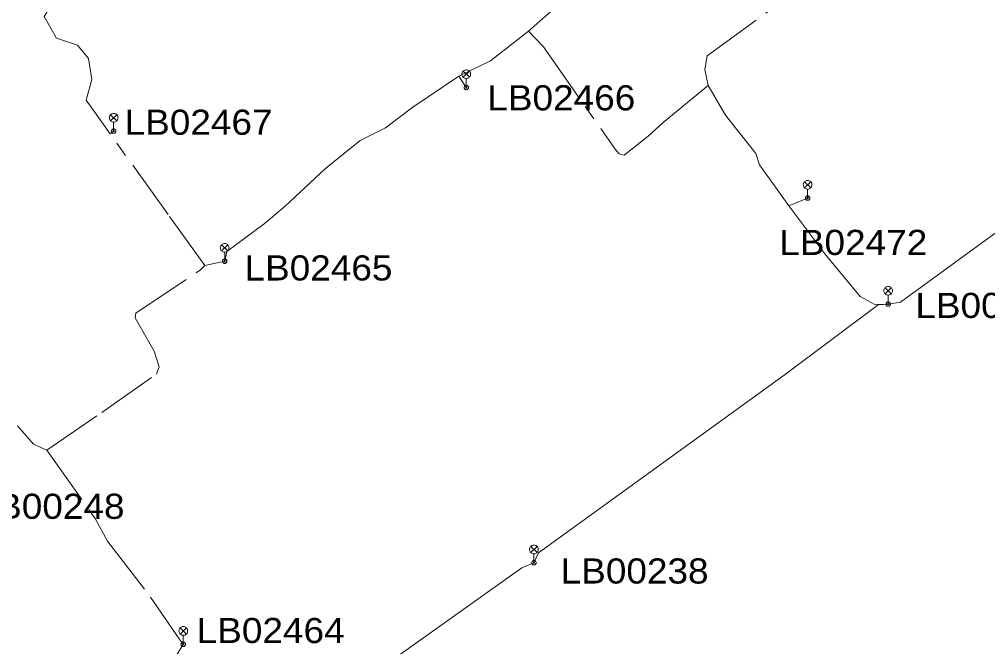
# Model space of a CAD drawing. Extents: x -688049 to -687261, y -973611 to -973038.
# Drawn here: x -687766.3 to -687682.8, y -973481.6 to -973427.5 of the extents above; entities that cross this region are included whole.
import ezdxf

# ---------------------------------------------------------------- set-up
doc = ezdxf.new("R2010")
doc.units = 0
doc.header["$LTSCALE"] = 0.87
doc.linetypes.add('LONG_DASH_SHORT_DASH', pattern=[9.9, 6, -1.2, 1.5, -1.2])
doc.layers.add('1', color=7, linetype='Continuous', lineweight=13)

msp = doc.modelspace()

# ---------------------------------------------------------------- linework, layer by layer
at = {"layer": '1'}
for p, q in [((-687728.025, -973431.965), (-687727.495, -973432.495)), ((-687728.025, -973432.495), (-687727.495, -973431.965)), ((-687727.76, -973433.38), (-687727.76, -973432.605)), ((-687758.455, -973435.725), (-687757.925, -973436.255)), ((-687758.455, -973436.255), (-687757.925, -973435.725)), ((-687758.19, -973437.14), (-687758.19, -973436.365)), ((-687698.565, -973441.505), (-687698.035, -973442.035)), ((-687698.565, -973442.035), (-687698.035, -973441.505)), ((-687698.3, -973442.92), (-687698.3, -973442.145)), ((-687748.875, -973446.945), (-687748.345, -973447.475)), ((-687748.875, -973447.475), (-687748.345, -973446.945)), ((-687748.61, -973448.36), (-687748.61, -973447.585)), ((-687691.615, -973450.645), (-687691.085, -973451.175)), ((-687691.615, -973451.175), (-687691.085, -973450.645)), ((-687691.35, -973452.06), (-687691.35, -973451.285)), ((-687722.185, -973472.955), (-687721.655, -973473.485)), ((-687722.185, -973473.485), (-687721.655, -973472.955)), ((-687721.92, -973474.37), (-687721.92, -973473.595)), ((-687752.445, -973479.985), (-687751.915, -973480.515)), ((-687752.445, -973480.515), (-687751.915, -973479.985)), ((-687752.18, -973481.4), (-687752.18, -973480.625))]:
    msp.add_line(p, q, dxfattribs=at)
at = {"layer": '1', "linetype": 'LONG_DASH_SHORT_DASH'}
for p, q in [((-687728.39, -973432.41), (-687727.76, -973433.38)), ((-687758.5, -973437.37), (-687758.19, -973437.14)), ((-687699.92, -973443.59), (-687698.3, -973442.92)), ((-687750.33, -973448.73), (-687748.61, -973448.36))]:
    msp.add_line(p, q, dxfattribs=at)
for points in [[(-687724.92, -973418.37), (-687719.49, -973425.59), (-687719.72, -973426.17), (-687722.38, -973428.53)], [(-687758.5, -973437.37), (-687760.56, -973434.47), (-687760.07, -973432.69), (-687760.35, -973430.88), (-687761.31, -973429.72), (-687763.11, -973429.13), (-687764.19, -973427.27), (-687763.32, -973425.88)], [(-687706.89, -973433.2), (-687707.18, -973431.82), (-687706.97, -973430.66), (-687700.3, -973425.8), (-687699.51, -973425.76)], [(-687722.38, -973428.53), (-687725.67, -973431.08), (-687728.39, -973432.41)], [(-687722.38, -973428.53), (-687721.1, -973429.88), (-687714.91, -973438.69), (-687714.57, -973439.11), (-687714.12, -973439.23), (-687712.06, -973437.58), (-687710.76, -973436.4), (-687706.89, -973433.2)], [(-687728.39, -973432.41), (-687732.37, -973435.09), (-687734.72, -973436.87), (-687736.91, -973437.95), (-687739.91, -973440.38), (-687743.38, -973443.62), (-687745.19, -973445.14), (-687748.41, -973447.53), (-687748.61, -973448.36)], [(-687699.92, -973443.59), (-687702.46, -973440.06), (-687702.77, -973439.08), (-687705.4, -973435.77), (-687706.89, -973433.2)], [(-687750.33, -973448.73), (-687753.5, -973444.33), (-687758.5, -973437.37)], [(-687691.34, -973452.07), (-687692.5, -973452.1), (-687693.77, -973451.41), (-687696.82, -973447.73), (-687699.92, -973443.59)], [(-687763.95, -973464.66), (-687759.21, -973461.4), (-687754.5, -973458.1), (-687754.26, -973457.46), (-687754.69, -973456.12), (-687756.33, -973453.24), (-687756.28, -973452.84), (-687750.71, -973449.12), (-687750.33, -973448.73)], [(-687766.48, -973462.57), (-687765.11, -973464.15), (-687763.95, -973464.66)], [(-687763.95, -973464.66), (-687759.79, -973470.54), (-687758.71, -973472.52), (-687755.01, -973477.33), (-687752.54, -973480.93), (-687752.18, -973481.4)], [(-687752.18, -973481.4), (-687752.93, -973482.67), (-687750.74, -973485.73), (-687749.13, -973487.38), (-687746.86, -973490.22), (-687747.02, -973490.93), (-687750.43, -973493.25), (-687752.29, -973494.69), (-687752.34, -973494.74)]]:
    msp.add_lwpolyline(points, dxfattribs=at)
at = {"layer": '1'}
for points in [[(-687727.385, -973432.23), (-687727.391, -973432.165), (-687727.408, -973432.102), (-687727.435, -973432.043), (-687727.473, -973431.989), (-687727.519, -973431.943), (-687727.572, -973431.905), (-687727.632, -973431.878), (-687727.695, -973431.861), (-687727.76, -973431.855), (-687727.825, -973431.861), (-687727.888, -973431.878), (-687727.948, -973431.905), (-687728.001, -973431.943), (-687728.047, -973431.989), (-687728.085, -973432.043), (-687728.112, -973432.102), (-687728.129, -973432.165), (-687728.135, -973432.23), (-687728.129, -973432.295), (-687728.112, -973432.358), (-687728.085, -973432.418), (-687728.047, -973432.471), (-687728.001, -973432.517), (-687727.948, -973432.555), (-687727.888, -973432.582), (-687727.825, -973432.599), (-687727.76, -973432.605), (-687727.695, -973432.599), (-687727.632, -973432.582), (-687727.572, -973432.555), (-687727.519, -973432.517), (-687727.473, -973432.471), (-687727.435, -973432.418), (-687727.408, -973432.358), (-687727.391, -973432.295)], [(-687727.57, -973433.38), (-687727.573, -973433.347), (-687727.581, -973433.315), (-687727.595, -973433.285), (-687727.614, -973433.258), (-687727.638, -973433.234), (-687727.665, -973433.215), (-687727.695, -973433.201), (-687727.727, -973433.193), (-687727.76, -973433.19), (-687727.793, -973433.193), (-687727.825, -973433.201), (-687727.855, -973433.215), (-687727.882, -973433.234), (-687727.906, -973433.258), (-687727.925, -973433.285), (-687727.939, -973433.315), (-687727.947, -973433.347), (-687727.95, -973433.38), (-687727.947, -973433.413), (-687727.939, -973433.445), (-687727.925, -973433.475), (-687727.906, -973433.502), (-687727.882, -973433.526), (-687727.855, -973433.545), (-687727.825, -973433.559), (-687727.793, -973433.567), (-687727.76, -973433.57), (-687727.727, -973433.567), (-687727.695, -973433.559), (-687727.665, -973433.545), (-687727.638, -973433.526), (-687727.614, -973433.502), (-687727.595, -973433.475), (-687727.581, -973433.445), (-687727.573, -973433.413)], [(-687727.71, -973433.38), (-687727.711, -973433.371), (-687727.713, -973433.363), (-687727.717, -973433.355), (-687727.722, -973433.348), (-687727.728, -973433.342), (-687727.735, -973433.337), (-687727.743, -973433.333), (-687727.751, -973433.331), (-687727.76, -973433.33), (-687727.769, -973433.331), (-687727.777, -973433.333), (-687727.785, -973433.337), (-687727.792, -973433.342), (-687727.798, -973433.348), (-687727.803, -973433.355), (-687727.807, -973433.363), (-687727.809, -973433.371), (-687727.81, -973433.38), (-687727.809, -973433.389), (-687727.807, -973433.397), (-687727.803, -973433.405), (-687727.798, -973433.412), (-687727.792, -973433.418), (-687727.785, -973433.423), (-687727.777, -973433.427), (-687727.769, -973433.429), (-687727.76, -973433.43), (-687727.751, -973433.429), (-687727.743, -973433.427), (-687727.735, -973433.423), (-687727.728, -973433.418), (-687727.722, -973433.412), (-687727.717, -973433.405), (-687727.713, -973433.397), (-687727.711, -973433.389)], [(-687757.815, -973435.99), (-687757.821, -973435.925), (-687757.838, -973435.862), (-687757.865, -973435.802), (-687757.903, -973435.749), (-687757.949, -973435.703), (-687758.003, -973435.665), (-687758.062, -973435.638), (-687758.125, -973435.621), (-687758.19, -973435.615), (-687758.255, -973435.621), (-687758.318, -973435.638), (-687758.378, -973435.665), (-687758.431, -973435.703), (-687758.477, -973435.749), (-687758.515, -973435.802), (-687758.542, -973435.862), (-687758.559, -973435.925), (-687758.565, -973435.99), (-687758.559, -973436.055), (-687758.542, -973436.118), (-687758.515, -973436.178), (-687758.477, -973436.231), (-687758.431, -973436.277), (-687758.378, -973436.315), (-687758.318, -973436.342), (-687758.255, -973436.359), (-687758.19, -973436.365), (-687758.125, -973436.359), (-687758.062, -973436.342), (-687758.003, -973436.315), (-687757.949, -973436.277), (-687757.903, -973436.231), (-687757.865, -973436.178), (-687757.838, -973436.118), (-687757.821, -973436.055)], [(-687758, -973437.14), (-687758.003, -973437.107), (-687758.011, -973437.075), (-687758.025, -973437.045), (-687758.044, -973437.018), (-687758.068, -973436.994), (-687758.095, -973436.975), (-687758.125, -973436.961), (-687758.157, -973436.953), (-687758.19, -973436.95), (-687758.223, -973436.953), (-687758.255, -973436.961), (-687758.285, -973436.975), (-687758.312, -973436.994), (-687758.336, -973437.018), (-687758.355, -973437.045), (-687758.369, -973437.075), (-687758.377, -973437.107), (-687758.38, -973437.14), (-687758.377, -973437.173), (-687758.369, -973437.205), (-687758.355, -973437.235), (-687758.336, -973437.262), (-687758.312, -973437.286), (-687758.285, -973437.305), (-687758.255, -973437.319), (-687758.223, -973437.327), (-687758.19, -973437.33), (-687758.157, -973437.327), (-687758.125, -973437.319), (-687758.095, -973437.305), (-687758.068, -973437.286), (-687758.044, -973437.262), (-687758.025, -973437.235), (-687758.011, -973437.205), (-687758.003, -973437.173)], [(-687758.14, -973437.14), (-687758.141, -973437.131), (-687758.143, -973437.123), (-687758.147, -973437.115), (-687758.152, -973437.108), (-687758.158, -973437.102), (-687758.165, -973437.097), (-687758.173, -973437.093), (-687758.181, -973437.091), (-687758.19, -973437.09), (-687758.199, -973437.091), (-687758.207, -973437.093), (-687758.215, -973437.097), (-687758.222, -973437.102), (-687758.228, -973437.108), (-687758.233, -973437.115), (-687758.237, -973437.123), (-687758.239, -973437.131), (-687758.24, -973437.14), (-687758.239, -973437.149), (-687758.237, -973437.157), (-687758.233, -973437.165), (-687758.228, -973437.172), (-687758.222, -973437.178), (-687758.215, -973437.183), (-687758.207, -973437.187), (-687758.199, -973437.189), (-687758.19, -973437.19), (-687758.181, -973437.189), (-687758.173, -973437.187), (-687758.165, -973437.183), (-687758.158, -973437.178), (-687758.152, -973437.172), (-687758.147, -973437.165), (-687758.143, -973437.157), (-687758.141, -973437.149)], [(-687697.925, -973441.77), (-687697.931, -973441.705), (-687697.948, -973441.642), (-687697.975, -973441.582), (-687698.013, -973441.529), (-687698.059, -973441.483), (-687698.112, -973441.445), (-687698.172, -973441.418), (-687698.235, -973441.401), (-687698.3, -973441.395), (-687698.365, -973441.401), (-687698.428, -973441.418), (-687698.488, -973441.445), (-687698.541, -973441.483), (-687698.587, -973441.529), (-687698.625, -973441.582), (-687698.652, -973441.642), (-687698.669, -973441.705), (-687698.675, -973441.77), (-687698.669, -973441.835), (-687698.652, -973441.898), (-687698.625, -973441.958), (-687698.587, -973442.011), (-687698.541, -973442.057), (-687698.488, -973442.095), (-687698.428, -973442.122), (-687698.365, -973442.139), (-687698.3, -973442.145), (-687698.235, -973442.139), (-687698.172, -973442.122), (-687698.112, -973442.095), (-687698.059, -973442.057), (-687698.013, -973442.011), (-687697.975, -973441.958), (-687697.948, -973441.898), (-687697.931, -973441.835)], [(-687698.11, -973442.92), (-687698.113, -973442.887), (-687698.121, -973442.855), (-687698.135, -973442.825), (-687698.154, -973442.798), (-687698.178, -973442.774), (-687698.205, -973442.755), (-687698.235, -973442.741), (-687698.267, -973442.733), (-687698.3, -973442.73), (-687698.333, -973442.733), (-687698.365, -973442.741), (-687698.395, -973442.755), (-687698.422, -973442.774), (-687698.446, -973442.798), (-687698.465, -973442.825), (-687698.479, -973442.855), (-687698.487, -973442.887), (-687698.49, -973442.92), (-687698.487, -973442.953), (-687698.479, -973442.985), (-687698.465, -973443.015), (-687698.446, -973443.042), (-687698.422, -973443.066), (-687698.395, -973443.085), (-687698.365, -973443.099), (-687698.333, -973443.107), (-687698.3, -973443.11), (-687698.267, -973443.107), (-687698.235, -973443.099), (-687698.205, -973443.085), (-687698.178, -973443.066), (-687698.154, -973443.042), (-687698.135, -973443.015), (-687698.121, -973442.985), (-687698.113, -973442.953)], [(-687698.25, -973442.92), (-687698.251, -973442.911), (-687698.253, -973442.903), (-687698.257, -973442.895), (-687698.262, -973442.888), (-687698.268, -973442.882), (-687698.275, -973442.877), (-687698.283, -973442.873), (-687698.291, -973442.871), (-687698.3, -973442.87), (-687698.309, -973442.871), (-687698.317, -973442.873), (-687698.325, -973442.877), (-687698.332, -973442.882), (-687698.338, -973442.888), (-687698.343, -973442.895), (-687698.347, -973442.903), (-687698.349, -973442.911), (-687698.35, -973442.92), (-687698.349, -973442.929), (-687698.347, -973442.937), (-687698.343, -973442.945), (-687698.338, -973442.952), (-687698.332, -973442.958), (-687698.325, -973442.963), (-687698.317, -973442.967), (-687698.309, -973442.969), (-687698.3, -973442.97), (-687698.291, -973442.969), (-687698.283, -973442.967), (-687698.275, -973442.963), (-687698.268, -973442.958), (-687698.262, -973442.952), (-687698.257, -973442.945), (-687698.253, -973442.937), (-687698.251, -973442.929)], [(-687748.235, -973447.21), (-687748.241, -973447.145), (-687748.258, -973447.082), (-687748.285, -973447.022), (-687748.323, -973446.969), (-687748.369, -973446.923), (-687748.422, -973446.885), (-687748.482, -973446.858), (-687748.545, -973446.841), (-687748.61, -973446.835), (-687748.675, -973446.841), (-687748.738, -973446.858), (-687748.798, -973446.885), (-687748.851, -973446.923), (-687748.897, -973446.969), (-687748.935, -973447.022), (-687748.962, -973447.082), (-687748.979, -973447.145), (-687748.985, -973447.21), (-687748.979, -973447.275), (-687748.962, -973447.338), (-687748.935, -973447.398), (-687748.897, -973447.451), (-687748.851, -973447.497), (-687748.798, -973447.535), (-687748.738, -973447.562), (-687748.675, -973447.579), (-687748.61, -973447.585), (-687748.545, -973447.579), (-687748.482, -973447.562), (-687748.422, -973447.535), (-687748.369, -973447.497), (-687748.323, -973447.451), (-687748.285, -973447.398), (-687748.258, -973447.338), (-687748.241, -973447.275)], [(-687748.42, -973448.36), (-687748.423, -973448.327), (-687748.431, -973448.295), (-687748.445, -973448.265), (-687748.464, -973448.238), (-687748.488, -973448.214), (-687748.515, -973448.195), (-687748.545, -973448.181), (-687748.577, -973448.173), (-687748.61, -973448.17), (-687748.643, -973448.173), (-687748.675, -973448.181), (-687748.705, -973448.195), (-687748.732, -973448.214), (-687748.756, -973448.238), (-687748.775, -973448.265), (-687748.789, -973448.295), (-687748.797, -973448.327), (-687748.8, -973448.36), (-687748.797, -973448.393), (-687748.789, -973448.425), (-687748.775, -973448.455), (-687748.756, -973448.482), (-687748.732, -973448.506), (-687748.705, -973448.525), (-687748.675, -973448.539), (-687748.643, -973448.547), (-687748.61, -973448.55), (-687748.577, -973448.547), (-687748.545, -973448.539), (-687748.515, -973448.525), (-687748.488, -973448.506), (-687748.464, -973448.482), (-687748.445, -973448.455), (-687748.431, -973448.425), (-687748.423, -973448.393)], [(-687748.56, -973448.36), (-687748.561, -973448.351), (-687748.563, -973448.343), (-687748.567, -973448.335), (-687748.572, -973448.328), (-687748.578, -973448.322), (-687748.585, -973448.317), (-687748.593, -973448.313), (-687748.601, -973448.311), (-687748.61, -973448.31), (-687748.619, -973448.311), (-687748.627, -973448.313), (-687748.635, -973448.317), (-687748.642, -973448.322), (-687748.648, -973448.328), (-687748.653, -973448.335), (-687748.657, -973448.343), (-687748.659, -973448.351), (-687748.66, -973448.36), (-687748.659, -973448.369), (-687748.657, -973448.377), (-687748.653, -973448.385), (-687748.648, -973448.392), (-687748.642, -973448.398), (-687748.635, -973448.403), (-687748.627, -973448.407), (-687748.619, -973448.409), (-687748.61, -973448.41), (-687748.601, -973448.409), (-687748.593, -973448.407), (-687748.585, -973448.403), (-687748.578, -973448.398), (-687748.572, -973448.392), (-687748.567, -973448.385), (-687748.563, -973448.377), (-687748.561, -973448.369)], [(-687690.975, -973450.91), (-687690.981, -973450.845), (-687690.998, -973450.782), (-687691.025, -973450.722), (-687691.063, -973450.669), (-687691.109, -973450.623), (-687691.162, -973450.585), (-687691.222, -973450.558), (-687691.285, -973450.541), (-687691.35, -973450.535), (-687691.415, -973450.541), (-687691.478, -973450.558), (-687691.538, -973450.585), (-687691.591, -973450.623), (-687691.637, -973450.669), (-687691.675, -973450.722), (-687691.702, -973450.782), (-687691.719, -973450.845), (-687691.725, -973450.91), (-687691.719, -973450.975), (-687691.702, -973451.038), (-687691.675, -973451.098), (-687691.637, -973451.151), (-687691.591, -973451.197), (-687691.538, -973451.235), (-687691.478, -973451.262), (-687691.415, -973451.279), (-687691.35, -973451.285), (-687691.285, -973451.279), (-687691.222, -973451.262), (-687691.162, -973451.235), (-687691.109, -973451.197), (-687691.063, -973451.151), (-687691.025, -973451.098), (-687690.998, -973451.038), (-687690.981, -973450.975)], [(-687691.16, -973452.06), (-687691.163, -973452.027), (-687691.171, -973451.995), (-687691.185, -973451.965), (-687691.204, -973451.938), (-687691.228, -973451.914), (-687691.255, -973451.895), (-687691.285, -973451.881), (-687691.317, -973451.873), (-687691.35, -973451.87), (-687691.383, -973451.873), (-687691.415, -973451.881), (-687691.445, -973451.895), (-687691.472, -973451.914), (-687691.496, -973451.938), (-687691.515, -973451.965), (-687691.529, -973451.995), (-687691.537, -973452.027), (-687691.54, -973452.06), (-687691.537, -973452.093), (-687691.529, -973452.125), (-687691.515, -973452.155), (-687691.496, -973452.182), (-687691.472, -973452.206), (-687691.445, -973452.225), (-687691.415, -973452.239), (-687691.383, -973452.247), (-687691.35, -973452.25), (-687691.317, -973452.247), (-687691.285, -973452.239), (-687691.255, -973452.225), (-687691.228, -973452.206), (-687691.204, -973452.182), (-687691.185, -973452.155), (-687691.171, -973452.125), (-687691.163, -973452.093)], [(-687691.3, -973452.06), (-687691.301, -973452.051), (-687691.303, -973452.043), (-687691.307, -973452.035), (-687691.312, -973452.028), (-687691.318, -973452.022), (-687691.325, -973452.017), (-687691.333, -973452.013), (-687691.341, -973452.011), (-687691.35, -973452.01), (-687691.359, -973452.011), (-687691.367, -973452.013), (-687691.375, -973452.017), (-687691.382, -973452.022), (-687691.388, -973452.028), (-687691.393, -973452.035), (-687691.397, -973452.043), (-687691.399, -973452.051), (-687691.4, -973452.06), (-687691.399, -973452.069), (-687691.397, -973452.077), (-687691.393, -973452.085), (-687691.388, -973452.092), (-687691.382, -973452.098), (-687691.375, -973452.103), (-687691.367, -973452.107), (-687691.359, -973452.109), (-687691.35, -973452.11), (-687691.341, -973452.109), (-687691.333, -973452.107), (-687691.325, -973452.103), (-687691.318, -973452.098), (-687691.312, -973452.092), (-687691.307, -973452.085), (-687691.303, -973452.077), (-687691.301, -973452.069)], [(-687721.545, -973473.22), (-687721.551, -973473.155), (-687721.568, -973473.092), (-687721.595, -973473.033), (-687721.633, -973472.979), (-687721.679, -973472.933), (-687721.732, -973472.895), (-687721.792, -973472.868), (-687721.855, -973472.851), (-687721.92, -973472.845), (-687721.985, -973472.851), (-687722.048, -973472.868), (-687722.108, -973472.895), (-687722.161, -973472.933), (-687722.207, -973472.979), (-687722.245, -973473.033), (-687722.272, -973473.092), (-687722.289, -973473.155), (-687722.295, -973473.22), (-687722.289, -973473.285), (-687722.272, -973473.348), (-687722.245, -973473.408), (-687722.207, -973473.461), (-687722.161, -973473.507), (-687722.108, -973473.545), (-687722.048, -973473.572), (-687721.985, -973473.589), (-687721.92, -973473.595), (-687721.855, -973473.589), (-687721.792, -973473.572), (-687721.732, -973473.545), (-687721.679, -973473.507), (-687721.633, -973473.461), (-687721.595, -973473.408), (-687721.568, -973473.348), (-687721.551, -973473.285)], [(-687721.73, -973474.37), (-687721.733, -973474.337), (-687721.741, -973474.305), (-687721.755, -973474.275), (-687721.774, -973474.248), (-687721.798, -973474.224), (-687721.825, -973474.205), (-687721.855, -973474.191), (-687721.887, -973474.183), (-687721.92, -973474.18), (-687721.953, -973474.183), (-687721.985, -973474.191), (-687722.015, -973474.205), (-687722.042, -973474.224), (-687722.066, -973474.248), (-687722.085, -973474.275), (-687722.099, -973474.305), (-687722.107, -973474.337), (-687722.11, -973474.37), (-687722.107, -973474.403), (-687722.099, -973474.435), (-687722.085, -973474.465), (-687722.066, -973474.492), (-687722.042, -973474.516), (-687722.015, -973474.535), (-687721.985, -973474.549), (-687721.953, -973474.557), (-687721.92, -973474.56), (-687721.887, -973474.557), (-687721.855, -973474.549), (-687721.825, -973474.535), (-687721.798, -973474.516), (-687721.774, -973474.492), (-687721.755, -973474.465), (-687721.741, -973474.435), (-687721.733, -973474.403)], [(-687721.87, -973474.37), (-687721.871, -973474.361), (-687721.873, -973474.353), (-687721.877, -973474.345), (-687721.882, -973474.338), (-687721.888, -973474.332), (-687721.895, -973474.327), (-687721.903, -973474.323), (-687721.911, -973474.321), (-687721.92, -973474.32), (-687721.929, -973474.321), (-687721.937, -973474.323), (-687721.945, -973474.327), (-687721.952, -973474.332), (-687721.958, -973474.338), (-687721.963, -973474.345), (-687721.967, -973474.353), (-687721.969, -973474.361), (-687721.97, -973474.37), (-687721.969, -973474.379), (-687721.967, -973474.387), (-687721.963, -973474.395), (-687721.958, -973474.402), (-687721.952, -973474.408), (-687721.945, -973474.413), (-687721.937, -973474.417), (-687721.929, -973474.419), (-687721.92, -973474.42), (-687721.911, -973474.419), (-687721.903, -973474.417), (-687721.895, -973474.413), (-687721.888, -973474.408), (-687721.882, -973474.402), (-687721.877, -973474.395), (-687721.873, -973474.387), (-687721.871, -973474.379)], [(-687751.805, -973480.25), (-687751.811, -973480.185), (-687751.828, -973480.122), (-687751.855, -973480.062), (-687751.893, -973480.009), (-687751.939, -973479.963), (-687751.992, -973479.925), (-687752.052, -973479.898), (-687752.115, -973479.881), (-687752.18, -973479.875), (-687752.245, -973479.881), (-687752.308, -973479.898), (-687752.368, -973479.925), (-687752.421, -973479.963), (-687752.467, -973480.009), (-687752.505, -973480.062), (-687752.532, -973480.122), (-687752.549, -973480.185), (-687752.555, -973480.25), (-687752.549, -973480.315), (-687752.532, -973480.378), (-687752.505, -973480.438), (-687752.467, -973480.491), (-687752.421, -973480.537), (-687752.368, -973480.575), (-687752.308, -973480.602), (-687752.245, -973480.619), (-687752.18, -973480.625), (-687752.115, -973480.619), (-687752.052, -973480.602), (-687751.992, -973480.575), (-687751.939, -973480.537), (-687751.893, -973480.491), (-687751.855, -973480.438), (-687751.828, -973480.378), (-687751.811, -973480.315)], [(-687751.99, -973481.4), (-687751.993, -973481.367), (-687752.001, -973481.335), (-687752.015, -973481.305), (-687752.034, -973481.278), (-687752.058, -973481.254), (-687752.085, -973481.235), (-687752.115, -973481.221), (-687752.147, -973481.213), (-687752.18, -973481.21), (-687752.213, -973481.213), (-687752.245, -973481.221), (-687752.275, -973481.235), (-687752.302, -973481.254), (-687752.326, -973481.278), (-687752.345, -973481.305), (-687752.359, -973481.335), (-687752.367, -973481.367), (-687752.37, -973481.4), (-687752.367, -973481.433), (-687752.359, -973481.465), (-687752.345, -973481.495), (-687752.326, -973481.522), (-687752.302, -973481.546), (-687752.275, -973481.565), (-687752.245, -973481.579), (-687752.213, -973481.587), (-687752.18, -973481.59), (-687752.147, -973481.587), (-687752.115, -973481.579), (-687752.085, -973481.565), (-687752.058, -973481.546), (-687752.034, -973481.522), (-687752.015, -973481.495), (-687752.001, -973481.465), (-687751.993, -973481.433)], [(-687752.13, -973481.4), (-687752.131, -973481.391), (-687752.133, -973481.383), (-687752.137, -973481.375), (-687752.142, -973481.368), (-687752.148, -973481.362), (-687752.155, -973481.357), (-687752.163, -973481.353), (-687752.171, -973481.351), (-687752.18, -973481.35), (-687752.189, -973481.351), (-687752.197, -973481.353), (-687752.205, -973481.357), (-687752.212, -973481.362), (-687752.218, -973481.368), (-687752.223, -973481.375), (-687752.227, -973481.383), (-687752.229, -973481.391), (-687752.23, -973481.4), (-687752.229, -973481.409), (-687752.227, -973481.417), (-687752.223, -973481.425), (-687752.218, -973481.432), (-687752.212, -973481.438), (-687752.205, -973481.443), (-687752.197, -973481.447), (-687752.189, -973481.449), (-687752.18, -973481.45), (-687752.171, -973481.449), (-687752.163, -973481.447), (-687752.155, -973481.443), (-687752.148, -973481.438), (-687752.142, -973481.432), (-687752.137, -973481.425), (-687752.133, -973481.417), (-687752.131, -973481.409)]]:
    msp.add_lwpolyline(points, close=True, dxfattribs=at)
for points in [[(-687665.65, -973433.21), (-687665.607, -973433.919), (-687690.297, -973451.9), (-687691.35, -973452.06)], [(-687691.35, -973452.06), (-687692.211, -973452.122), (-687700.329, -973458.187), (-687721.526, -973473.512), (-687721.92, -973474.37)], [(-687721.92, -973474.37), (-687722.962, -973474.805), (-687741.711, -973488.143), (-687751.504, -973495.468), (-687752.07, -973496.37)]]:
    msp.add_lwpolyline(points, dxfattribs=at)

# ---------------------------------------------------------------- texts
at = {"layer": '1', "width": 1.1}
for s, height, p in [('LB02466', 2.168, (-687725.942, -973435.351)), ('LB02467', 2.168, (-687757.247, -973437.459)), ('LB02472', 2.168, (-687700.745, -973447.824)), ('LB02465', 2.168, (-687746.9, -973450.026)), ('LB00239', 2.167, (-687689.004, -973453.257)), ('LB00248', 2.167, (-687770.017, -973470.583)), ('LB00238', 2.167, (-687719.613, -973476.163)), ('LB02464', 2.168, (-687751.027, -973481.297))]:
    msp.add_text(s, height=height, dxfattribs=at).set_placement(p)

doc.saveas('drawing.dxf')
